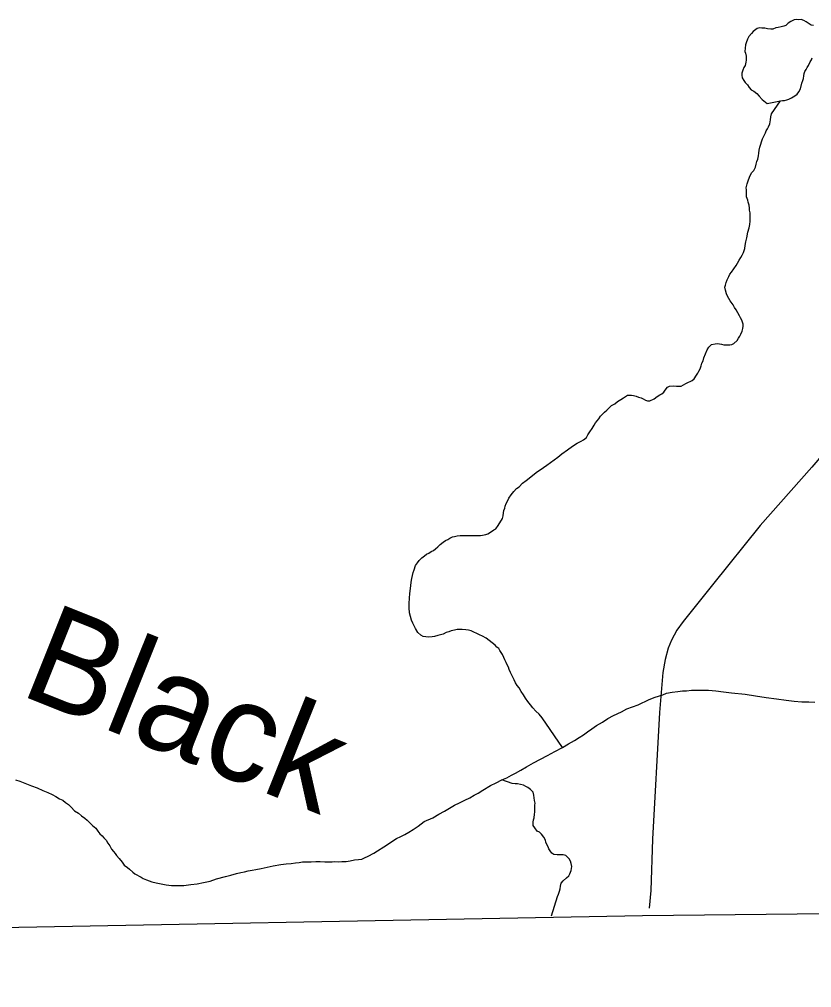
# Model space of a CAD drawing. Extents: x -10.1 to 68, y -9.5 to 29.2.
# Drawn here: x 5.651 to 6.404, y 16.795 to 17.716 of the extents above; entities that cross this region are included whole.
import ezdxf

# ---------------------------------------------------------------- set-up
doc = ezdxf.new("R2010")
doc.units = 0
for name, color, linetype in [('GM_X_Adjacent_County', 7, 'Continuous'), ('GM_X_Minor_Lake', 7, 'Continuous'), ('GM_X_Minor_River', 7, 'Continuous'), ('GM_X_Minor_River_Text', 7, 'Continuous'), ('GM_X_Township_Road', 7, 'Continuous')]:
    doc.layers.add(name, color=color, linetype=linetype)

msp = doc.modelspace()

# ---------------------------------------------------------------- linework, layer by layer
at = {"layer": 'GM_X_Adjacent_County'}
msp.add_lwpolyline([(8.9, 16.89673), (8.50227, 16.89039), (7.96653, 16.88211), (7.52326, 16.87745), (6.50832, 16.86667), (6.24349, 16.86385), (4.82059, 16.83722), (4.16319, 16.82854), (3.6875, 16.82225), (2.80446, 16.80799), (2.1, 16.79545)], dxfattribs=at)
at = {"layer": 'GM_X_Minor_Lake'}
for points in [[(6.40612, 17.71067), (6.40383, 17.711), (6.4019, 17.71209), (6.3992, 17.71394), (6.39688, 17.71541), (6.39458, 17.71611), (6.3923, 17.71606), (6.38963, 17.71638), (6.38774, 17.71596), (6.38473, 17.71437), (6.3821, 17.71279), (6.37987, 17.71045), (6.37798, 17.71003), (6.37533, 17.7092), (6.37268, 17.70876), (6.37041, 17.70833), (6.36739, 17.70712), (6.36549, 17.70708), (6.36244, 17.70739), (6.35976, 17.70809), (6.3571, 17.70803), (6.35481, 17.70835), (6.35254, 17.70754), (6.3488, 17.70479), (6.34732, 17.70286), (6.34472, 17.70013), (6.34326, 17.69744), (6.3422, 17.69399), (6.34148, 17.69207), (6.34117, 17.68902), (6.34086, 17.68597), (6.34166, 17.68408), (6.3421, 17.68143), (6.34219, 17.67762), (6.34185, 17.67572), (6.34116, 17.67265), (6.34007, 17.67073), (6.33899, 17.66804), (6.33791, 17.66535), (6.33795, 17.66345), (6.33839, 17.66079), (6.33997, 17.65817), (6.34116, 17.65629), (6.34349, 17.65406), (6.34507, 17.65144), (6.34703, 17.6492), (6.34933, 17.64811), (6.35243, 17.6459), (6.35439, 17.64328), (6.3575, 17.6403), (6.36216, 17.63623), (6.37466, 17.63879)], [(6.39662, 17.66022), (6.39695, 17.66252), (6.39727, 17.66481), (6.39799, 17.66672), (6.39909, 17.66865), (6.40019, 17.67058), (6.40128, 17.67251), (6.40311, 17.67597), (6.40421, 17.6779), (6.40492, 17.67982)], [(6.37466, 17.63879), (6.37656, 17.63922), (6.37845, 17.63926), (6.38073, 17.63969), (6.38261, 17.6405), (6.38525, 17.6417), (6.38825, 17.64367), (6.39049, 17.64525), (6.39234, 17.64757), (6.3938, 17.65027), (6.3952, 17.65563), (6.3959, 17.65831), (6.39662, 17.66022)]]:
    msp.add_lwpolyline(points, dxfattribs=at)
at = {"layer": 'GM_X_Minor_River'}
for points in [[(6.33712, 17.41686), (6.33819, 17.41993), (6.3389, 17.42223), (6.33923, 17.42452), (6.33919, 17.42642), (6.33876, 17.42831), (6.33796, 17.4302), (6.33677, 17.43245), (6.33596, 17.43434), (6.33437, 17.43735), (6.33279, 17.43997), (6.33121, 17.44222), (6.32963, 17.44485), (6.32688, 17.44859), (6.32569, 17.45085), (6.3245, 17.4531), (6.3233, 17.45536), (6.32247, 17.45876), (6.32202, 17.4618), (6.32235, 17.46371), (6.32306, 17.46601), (6.32414, 17.46869), (6.32559, 17.47177), (6.32668, 17.47408), (6.32816, 17.47602), (6.33258, 17.4822), (6.33405, 17.48452), (6.33551, 17.48722), (6.33697, 17.48992), (6.33844, 17.49223), (6.33953, 17.49454), (6.34025, 17.49646), (6.34096, 17.49838), (6.34127, 17.50143), (6.34196, 17.50487), (6.34263, 17.50869), (6.34365, 17.51404), (6.34508, 17.51826), (6.34577, 17.52132), (6.34608, 17.52437), (6.34602, 17.52703), (6.34596, 17.52969), (6.34589, 17.53236), (6.34545, 17.53501), (6.34541, 17.53691), (6.34497, 17.53956), (6.34414, 17.54259), (6.34371, 17.54448), (6.3425, 17.5475), (6.34245, 17.54978), (6.34239, 17.55244), (6.34235, 17.55434), (6.3423, 17.55625), (6.34298, 17.56007), (6.34441, 17.5639), (6.34585, 17.56774), (6.34768, 17.57083), (6.34954, 17.57277), (6.35099, 17.57585), (6.35169, 17.57853), (6.35239, 17.58121), (6.3531, 17.58351), (6.35379, 17.58657), (6.35411, 17.58924), (6.35442, 17.59191), (6.35512, 17.59497), (6.3576, 17.60264), (6.35906, 17.60533), (6.36052, 17.60841), (6.36123, 17.61033), (6.36233, 17.61226), (6.36343, 17.61419), (6.36451, 17.61687), (6.36518, 17.62069), (6.36549, 17.62375), (6.36619, 17.62643), (6.37466, 17.63879)], [(6.1043, 17.23194), (6.10652, 17.23504), (6.11055, 17.2416), (6.11125, 17.24428), (6.11157, 17.24695), (6.1119, 17.24924), (6.11261, 17.25154), (6.11294, 17.25345), (6.11403, 17.25576), (6.11512, 17.25806), (6.11657, 17.26114), (6.11878, 17.26424), (6.12138, 17.26734), (6.12398, 17.27006), (6.12622, 17.27164), (6.12957, 17.27514), (6.13293, 17.27788), (6.13742, 17.2814), (6.14265, 17.28533), (6.1494, 17.29005), (6.15277, 17.29241), (6.15614, 17.29477), (6.1595, 17.29751), (6.16325, 17.29988), (6.16698, 17.30301), (6.17222, 17.30693), (6.17709, 17.31047), (6.18159, 17.31323), (6.18535, 17.31522), (6.1876, 17.31641), (6.19021, 17.31876), (6.19168, 17.32107), (6.19351, 17.32416), (6.19573, 17.32725), (6.19756, 17.33034), (6.19903, 17.33266), (6.2005, 17.33459), (6.20198, 17.33653), (6.20383, 17.33886), (6.20569, 17.3408), (6.20755, 17.34274), (6.20978, 17.3447), (6.21164, 17.34664), (6.21425, 17.34899), (6.21726, 17.35058), (6.21987, 17.35292), (6.22287, 17.35489), (6.2255, 17.35647), (6.22737, 17.35766), (6.22925, 17.35884), (6.23305, 17.35893), (6.23496, 17.35859), (6.23764, 17.35789), (6.23994, 17.35718), (6.24224, 17.35647), (6.24417, 17.35538), (6.24647, 17.35429), (6.24839, 17.35357), (6.25067, 17.35362), (6.25481, 17.35562), (6.25743, 17.35758), (6.26006, 17.35917), (6.26194, 17.36035), (6.2638, 17.36191), (6.26528, 17.36385), (6.2675, 17.36657), (6.26938, 17.36737), (6.2728, 17.36783), (6.27585, 17.36752), (6.27851, 17.36758), (6.28041, 17.36762), (6.28267, 17.36881), (6.28492, 17.37001), (6.28718, 17.3712), (6.28906, 17.37201), (6.29095, 17.37281), (6.29281, 17.37437), (6.29502, 17.37785), (6.29612, 17.37978), (6.29721, 17.3817), (6.2983, 17.38401), (6.29938, 17.3867), (6.30008, 17.38938), (6.30117, 17.39169), (6.30187, 17.39437), (6.30512, 17.40205), (6.30658, 17.40475), (6.30919, 17.40709), (6.31259, 17.40793), (6.31488, 17.40798), (6.31679, 17.40765), (6.3187, 17.40731), (6.32099, 17.40698), (6.32404, 17.40667), (6.3267, 17.40673), (6.32859, 17.40715), (6.33048, 17.40796), (6.33345, 17.41107), (6.33493, 17.41301), (6.33602, 17.41493), (6.33712, 17.41686)], [(6.16767, 17.02373), (6.14837, 17.05221), (6.14525, 17.05557), (6.14213, 17.05854), (6.1394, 17.06152), (6.13705, 17.06451), (6.1347, 17.0675), (6.13234, 17.07087), (6.13037, 17.07387), (6.12839, 17.07725), (6.12641, 17.08063), (6.12446, 17.08287), (6.12287, 17.08549), (6.12167, 17.08813), (6.11928, 17.09264), (6.11809, 17.09528), (6.11688, 17.09791), (6.11607, 17.10018), (6.11488, 17.10244), (6.11406, 17.1047), (6.11286, 17.10733), (6.11167, 17.10959), (6.11047, 17.11223), (6.10928, 17.1141), (6.1081, 17.11598), (6.10691, 17.11785), (6.10498, 17.11933), (6.10341, 17.1212), (6.09489, 17.12785), (6.09142, 17.12968), (6.08873, 17.13114), (6.08604, 17.13222), (6.08334, 17.13368), (6.08065, 17.13476), (6.07835, 17.13547), (6.07568, 17.13579), (6.07225, 17.13609), (6.07035, 17.13604), (6.06731, 17.13597), (6.06503, 17.13554), (6.06163, 17.1347), (6.05937, 17.13389), (6.0571, 17.13308), (6.0541, 17.13149), (6.04918, 17.13023), (6.04577, 17.12939), (6.0435, 17.12896), (6.04045, 17.12889), (6.03778, 17.12921), (6.03511, 17.12953), (6.03281, 17.13062), (6.03008, 17.13322), (6.02771, 17.13697), (6.02651, 17.13961), (6.02531, 17.14224), (6.02411, 17.14488), (6.02204, 17.15206), (6.02194, 17.15663), (6.02184, 17.16081), (6.02211, 17.16576), (6.02238, 17.17033), (6.02336, 17.17759), (6.02366, 17.18102), (6.02434, 17.18446), (6.02574, 17.1902), (6.02643, 17.19288), (6.02786, 17.1971), (6.02971, 17.19942), (6.03118, 17.20174), (6.03379, 17.20408), (6.03641, 17.20604), (6.03827, 17.20761), (6.04053, 17.2088), (6.04278, 17.21037), (6.04504, 17.21118), (6.04691, 17.21275), (6.04914, 17.2147), (6.05138, 17.21704), (6.05399, 17.219), (6.05624, 17.22057), (6.0585, 17.22177), (6.06037, 17.22295), (6.06301, 17.22415), (6.0649, 17.22458), (6.06756, 17.22502), (6.07021, 17.22546), (6.07401, 17.22554), (6.07781, 17.22563), (6.08277, 17.22536), (6.08695, 17.22546), (6.08961, 17.22552), (6.0915, 17.22594), (6.09454, 17.22639), (6.09642, 17.2272), (6.09831, 17.228), (6.10243, 17.23076), (6.1043, 17.23194)], [(5.86861, 16.90657), (5.87241, 16.90703), (5.87619, 16.90788), (5.88112, 16.90875), (5.8868, 16.91002), (5.89247, 16.91129), (5.89967, 16.9126), (5.90499, 16.9131), (5.90954, 16.91358), (5.91372, 16.91406), (5.91713, 16.91452), (5.92055, 16.91498), (5.92435, 16.91506), (5.92853, 16.91516), (5.9331, 16.91526), (5.93728, 16.91536), (5.94147, 16.91508), (5.94527, 16.91516), (5.9487, 16.91524), (5.95098, 16.91529), (5.95441, 16.91499), (5.95782, 16.91545), (5.96201, 16.91554), (5.9658, 16.91601), (5.96997, 16.91687), (5.97376, 16.91733), (5.9768, 16.91778), (5.97943, 16.91899), (5.98282, 16.92059), (5.98808, 16.92337), (6.00121, 16.93166), (6.00533, 16.93442), (6.00984, 16.93718), (6.01398, 16.93918), (6.01774, 16.94117), (6.02149, 16.94316), (6.02562, 16.94591), (6.03049, 16.94907), (6.0361, 16.95338), (6.04439, 16.957), (6.05001, 16.96055), (6.05528, 16.96333), (6.06016, 16.96611), (6.06504, 16.96888), (6.06956, 16.97127), (6.07483, 16.97367), (6.07934, 16.97606), (6.08347, 16.97844), (6.08723, 16.98042), (6.09173, 16.98319), (6.09924, 16.98755), (6.1045, 16.99033), (6.10977, 16.99311), (6.11467, 16.99513), (6.11918, 16.99751), (6.12294, 16.9995), (6.12782, 17.00228), (6.13346, 17.00545), (6.13983, 17.0094), (6.14661, 17.0126), (6.15338, 17.01618), (6.16013, 17.02014), (6.16767, 17.02373), (6.17329, 17.02729), (6.17892, 17.03046), (6.18343, 17.03323), (6.18755, 17.03598), (6.19129, 17.03873), (6.19542, 17.04149), (6.19991, 17.04464), (6.20554, 17.04781), (6.21079, 17.05136), (6.21605, 17.05414), (6.22358, 17.05773), (6.22884, 17.06052), (6.2394, 17.06456), (6.24995, 17.06937), (6.2556, 17.07178), (6.26278, 17.07385), (6.26655, 17.07546), (6.27186, 17.07634), (6.27716, 17.07722), (6.28172, 17.07771), (6.28552, 17.07779), (6.29008, 17.07828), (6.29502, 17.07839), (6.30035, 17.07851), (6.30644, 17.07827), (6.3133, 17.07767), (6.32055, 17.07669), (6.32818, 17.07573), (6.34115, 17.0745), (6.35108, 17.07283), (6.361, 17.07153), (6.37092, 17.07024), (6.38009, 17.06892), (6.38772, 17.06796), (6.39496, 17.06736), (6.40182, 17.06714), (6.40753, 17.06689)], [(5.64746, 16.99322), (5.65168, 16.9918), (5.65629, 16.99), (5.66281, 16.98749), (5.66819, 16.98533), (5.67357, 16.98279), (5.67818, 16.98099), (5.68241, 16.97918), (5.68587, 16.97736), (5.68935, 16.97515), (5.69243, 16.9737), (5.69514, 16.97148), (5.69785, 16.96964), (5.70057, 16.96704), (5.70369, 16.96369), (5.70754, 16.96149), (5.71027, 16.95889), (5.71336, 16.95668), (5.71569, 16.95483), (5.71802, 16.9526), (5.72075, 16.94961), (5.72385, 16.94702), (5.72582, 16.9444), (5.72778, 16.94178), (5.73011, 16.93994), (5.73167, 16.93807), (5.73363, 16.93583), (5.73522, 16.93282), (5.73718, 16.9302), (5.73877, 16.9272), (5.74072, 16.92496), (5.74229, 16.92309), (5.74347, 16.92122), (5.7462, 16.91823), (5.74895, 16.91487), (5.75092, 16.91187), (5.75401, 16.90966), (5.75595, 16.90818), (5.75906, 16.90521), (5.76099, 16.90373), (5.76716, 16.90045), (5.76909, 16.89935), (5.77216, 16.8979), (5.77715, 16.89611), (5.78136, 16.89506), (5.78595, 16.89403), (5.79091, 16.89338), (5.79587, 16.89273), (5.80159, 16.89248), (5.80767, 16.89262), (5.81412, 16.89353), (5.82019, 16.89404), (5.82625, 16.89533), (5.83269, 16.89661), (5.83872, 16.89904), (5.84705, 16.90113), (5.85235, 16.90239), (5.85763, 16.90403), (5.8618, 16.90489), (5.8652, 16.90572), (5.86861, 16.90657)], [(6.15723, 16.86362), (6.16291, 16.88208), (6.16362, 16.88438), (6.1647, 16.88707), (6.16541, 16.88937), (6.16573, 16.89204), (6.16643, 16.89472), (6.16828, 16.89704), (6.17126, 16.89977), (6.1735, 16.90173), (6.1746, 16.90365), (6.17567, 16.90672), (6.17634, 16.91054), (6.17589, 16.91358), (6.17508, 16.91584), (6.17389, 16.9181), (6.17077, 16.92107), (6.16809, 16.92177), (6.16467, 16.92169), (6.16239, 16.92164), (6.15934, 16.92195), (6.1574, 16.92343), (6.15583, 16.92568), (6.15464, 16.92755), (6.15384, 16.92944), (6.15226, 16.93206), (6.15184, 16.93396), (6.15141, 16.93585), (6.14983, 16.93847), (6.14748, 16.94147), (6.14553, 16.94333), (6.14361, 16.94442), (6.14125, 16.94741), (6.13968, 16.94966), (6.13961, 16.9527), (6.13994, 16.95499), (6.14066, 16.95691), (6.14096, 16.96034), (6.14129, 16.96225), (6.14125, 16.96415), (6.1412, 16.96644), (6.14114, 16.9691), (6.14148, 16.97101), (6.14104, 16.97328), (6.1406, 16.97594), (6.14016, 16.97859), (6.13972, 16.98124), (6.13699, 16.98384), (6.13467, 16.98569), (6.13274, 16.98679), (6.13043, 16.98788), (6.12776, 16.98858), (6.1247, 16.98927), (6.12241, 16.98922), (6.11974, 16.98954), (6.10977, 16.99311)]]:
    msp.add_lwpolyline(points, dxfattribs=at)
at = {"layer": 'GM_X_Township_Road'}
msp.add_lwpolyline([(6.51598, 17.42102), (6.51411, 17.4188), (6.48253, 17.38129), (6.42687, 17.31642), (6.40442, 17.29061), (6.35549, 17.23495), (6.31016, 17.17861), (6.28232, 17.14382), (6.27626, 17.13552), (6.2711, 17.12587), (6.26796, 17.11824), (6.26504, 17.10769), (6.26302, 17.09512), (6.25965, 17.05719), (6.25315, 16.93666), (6.25157, 16.88795), (6.25, 16.87112)], dxfattribs=at)

# ---------------------------------------------------------------- texts
at = {"layer": 'GM_X_Minor_River_Text'}
msp.add_text('Black', height=0.094749, rotation=338.20076, dxfattribs=at).set_placement((5.64963, 17.07471))

doc.saveas('drawing.dxf')
